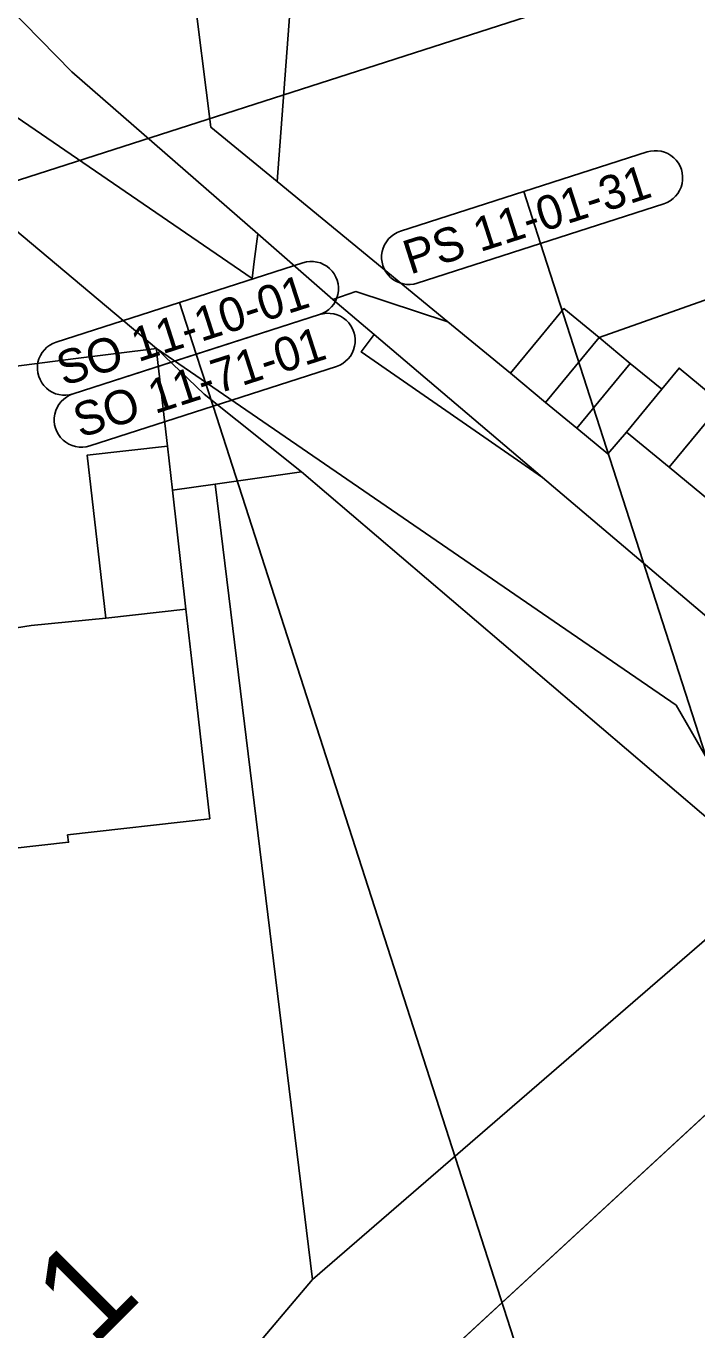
# Model space of a CAD drawing. Extents: x -758836 to -757729, y -1175316 to -1174366.
# Drawn here: x -758483.3 to -758434.1, y -1174861 to -1174765.3 of the extents above; entities that cross this region are included whole.
import ezdxf

# ---------------------------------------------------------------- set-up
doc = ezdxf.new("R2010")
doc.units = 0
for name, color, linetype in [('_NOR-pomocná', 7, 'Continuous'), ('_NOR-popis', 7, 'Continuous'), ('G_Obvod stavby', 7, 'Continuous'), ('Hranice parcel', 7, 'Continuous'), ('Vrstva 7', 7, 'Continuous')]:
    doc.layers.add(name, color=color, linetype=linetype)

msp = doc.modelspace()

# ---------------------------------------------------------------- linework, layer by layer
at = {"layer": '_NOR-pomocná'}
for p, q in [((-758446.776, -1174777.414), (-758445.549, -1174781.221)), ((-758472.016, -1174785.544), (-758470.79, -1174789.351)), ((-758470.79, -1174789.351), (-758469.563, -1174793.158))]:
    msp.add_line(p, q, dxfattribs=at)
msp.add_lwpolyline([(-758517.538, -1174787.416), (-758417.595, -1174755.224), (-758372.066, -1174896.572), (-758472.009, -1174928.764)], close=True, dxfattribs=at)
at = {"layer": '_NOR-popis'}
for points in [[(-758455.818, -1174780.326), (-758437.733, -1174774.501)], [(-758436.507, -1174778.308), (-758445.549, -1174781.221), (-758425.724, -1174842.771)], [(-758445.549, -1174781.221), (-758454.592, -1174784.134)], [(-758481.059, -1174788.456), (-758462.974, -1174782.631)], [(-758479.832, -1174792.264), (-758461.747, -1174786.438)], [(-758461.747, -1174786.439), (-758470.79, -1174789.351)], [(-758470.79, -1174789.351), (-758479.832, -1174792.264)], [(-758460.521, -1174790.246), (-758469.563, -1174793.158), (-758441.828, -1174879.266)], [(-758469.563, -1174793.158), (-758478.606, -1174796.071)]]:
    msp.add_lwpolyline(points, dxfattribs=at)
for centre, start, end in [((-758437.12, -1174776.405), 287.85331, 107.85402), ((-758455.205, -1174782.23), 107.85402, 287.85473), ((-758462.36, -1174784.535), 287.85331, 107.85402), ((-758461.134, -1174788.342), 287.85331, 107.85402), ((-758480.445, -1174790.36), 107.85402, 287.85473), ((-758479.219, -1174794.167), 107.85402, 287.85473)]:
    msp.add_arc(centre, 2, start, end, dxfattribs=at)
at = {"layer": 'G_Obvod stavby'}
msp.add_lwpolyline([(-758424.368, -1174835.441), (-758423.81, -1174836.28), (-758457.56, -1174867.46)], dxfattribs=at)
at = {"layer": 'Hranice parcel'}
for p, q in [((-758464.86, -1174776.68), (-758452.34, -1174786.98)), ((-758466.28, -1174780.52), (-758460.78, -1174785.32)), ((-758441.25, -1174788.13), (-758430.32, -1174784.25)), ((-758460.78, -1174785.32), (-758457.74, -1174787.91)), ((-758452.34, -1174786.98), (-758447.76, -1174790.74)), ((-758457.74, -1174787.91), (-758445.41, -1174798.39)), ((-758441.25, -1174788.13), (-758445.18, -1174792.88)), ((-758438.96, -1174790.02), (-758441.25, -1174788.13)), ((-758442.89, -1174794.78), (-758438.96, -1174790.02)), ((-758436.66, -1174791.92), (-758438.96, -1174790.02)), ((-758447.76, -1174790.74), (-758445.18, -1174792.88)), ((-758436.66, -1174791.92), (-758439.24, -1174795.07)), ((-758445.18, -1174792.88), (-758442.89, -1174794.78)), ((-758436.12, -1174797.63), (-758432.25, -1174792.96)), ((-758439.24, -1174795.07), (-758436.12, -1174797.63)), ((-758472.54, -1174799.33), (-758472.91, -1174796.09)), ((-758463.07, -1174797.97), (-758469.41, -1174798.88)), ((-758431.12, -1174825.29), (-758463.07, -1174797.97)), ((-758436.12, -1174797.63), (-758433, -1174800.2)), ((-758469.41, -1174798.88), (-758472.54, -1174799.33)), ((-758469.41, -1174798.88), (-758462.28, -1174857.27)), ((-758445.41, -1174798.39), (-758405.64, -1174832.2)), ((-758471.55, -1174808.06), (-758472.54, -1174799.33)), ((-758471.55, -1174808.06), (-758477.43, -1174808.72)), ((-758470.75, -1174815.07), (-758471.55, -1174808.06)), ((-758462.28, -1174857.27), (-758431.14, -1174830.31)), ((-758457.56, -1174867.46), (-758423.81, -1174836.28)), ((-758496.7, -1174897.94), (-758462.28, -1174857.27))]:
    msp.add_line(p, q, dxfattribs=at)
for points in [[(-758466.28, -1174780.52), (-758466.54, -1174782.53), (-758466.7, -1174783.79), (-758499, -1174761.63), (-758510.58, -1174750.09), (-758507.04, -1174746.79), (-758503.32, -1174743.41)], [(-758463.12, -1174748.03), (-758463.07, -1174752.81), (-758464.86, -1174776.68)], [(-758497.78, -1174750.4), (-758491.43, -1174756.87), (-758486.91, -1174761.48), (-758479.92, -1174768.61), (-758466.28, -1174780.52)], [(-758471.06, -1174761.99), (-758469.72, -1174772.68), (-758464.86, -1174776.68)], [(-758473.72, -1174788.92), (-758496.19, -1174770.04), (-758501.06, -1174765.48)], [(-758460.78, -1174785.32), (-758459.09, -1174784.75), (-758452.34, -1174786.98)], [(-758441.25, -1174788.13), (-758443.83, -1174786), (-758445.52, -1174788.04), (-758447.76, -1174790.74)], [(-758445.41, -1174798.39), (-758458.69, -1174789.18), (-758457.74, -1174787.91)], [(-758473.72, -1174788.92), (-758479.82, -1174789.69), (-758484.93, -1174790.34), (-758492.23, -1174791.3)], [(-758463.07, -1174797.97), (-758470.22, -1174792.27), (-758473.72, -1174788.92)], [(-758473.72, -1174788.92), (-758444.54, -1174808.96), (-758435.6, -1174815.1), (-758434.13, -1174817.65), (-758432.32, -1174820.8), (-758431.12, -1174825.29)], [(-758472.91, -1174796.09), (-758473.68, -1174789.31), (-758473.72, -1174788.92)], [(-758432.25, -1174792.96), (-758435.38, -1174790.37), (-758436.66, -1174791.92)], [(-758442.89, -1174794.78), (-758440.6, -1174796.67), (-758439.24, -1174795.07)], [(-758477.43, -1174808.72), (-758478.79, -1174796.75), (-758472.91, -1174796.09)], [(-758489.99, -1174810.38), (-758482.89, -1174809.27), (-758477.43, -1174808.72)], [(-758488.24, -1174825.29), (-758484.39, -1174824.82), (-758484.3, -1174825.64), (-758480.16, -1174825.17), (-758480.23, -1174824.63), (-758469.8, -1174823.45), (-758470.75, -1174815.07)]]:
    msp.add_lwpolyline(points, dxfattribs=at)

# ---------------------------------------------------------------- texts
at = {"layer": '_NOR-popis'}
for s, p in [('PS 11-01-31', (-758455.11, -1174783.513)), ('SO 11-10-01', (-758480.535, -1174791.702)), ('SO 11-71-01', (-758479.308, -1174795.509))]:
    msp.add_text(s, height=2.5, rotation=17.85402, dxfattribs=at).set_placement(p)
at = {"layer": 'Vrstva 7'}
msp.add_text('106,1', height=6.9716, rotation=44.96826, dxfattribs=at).set_placement((-758491.204, -1174875.133))

doc.saveas('drawing.dxf')
